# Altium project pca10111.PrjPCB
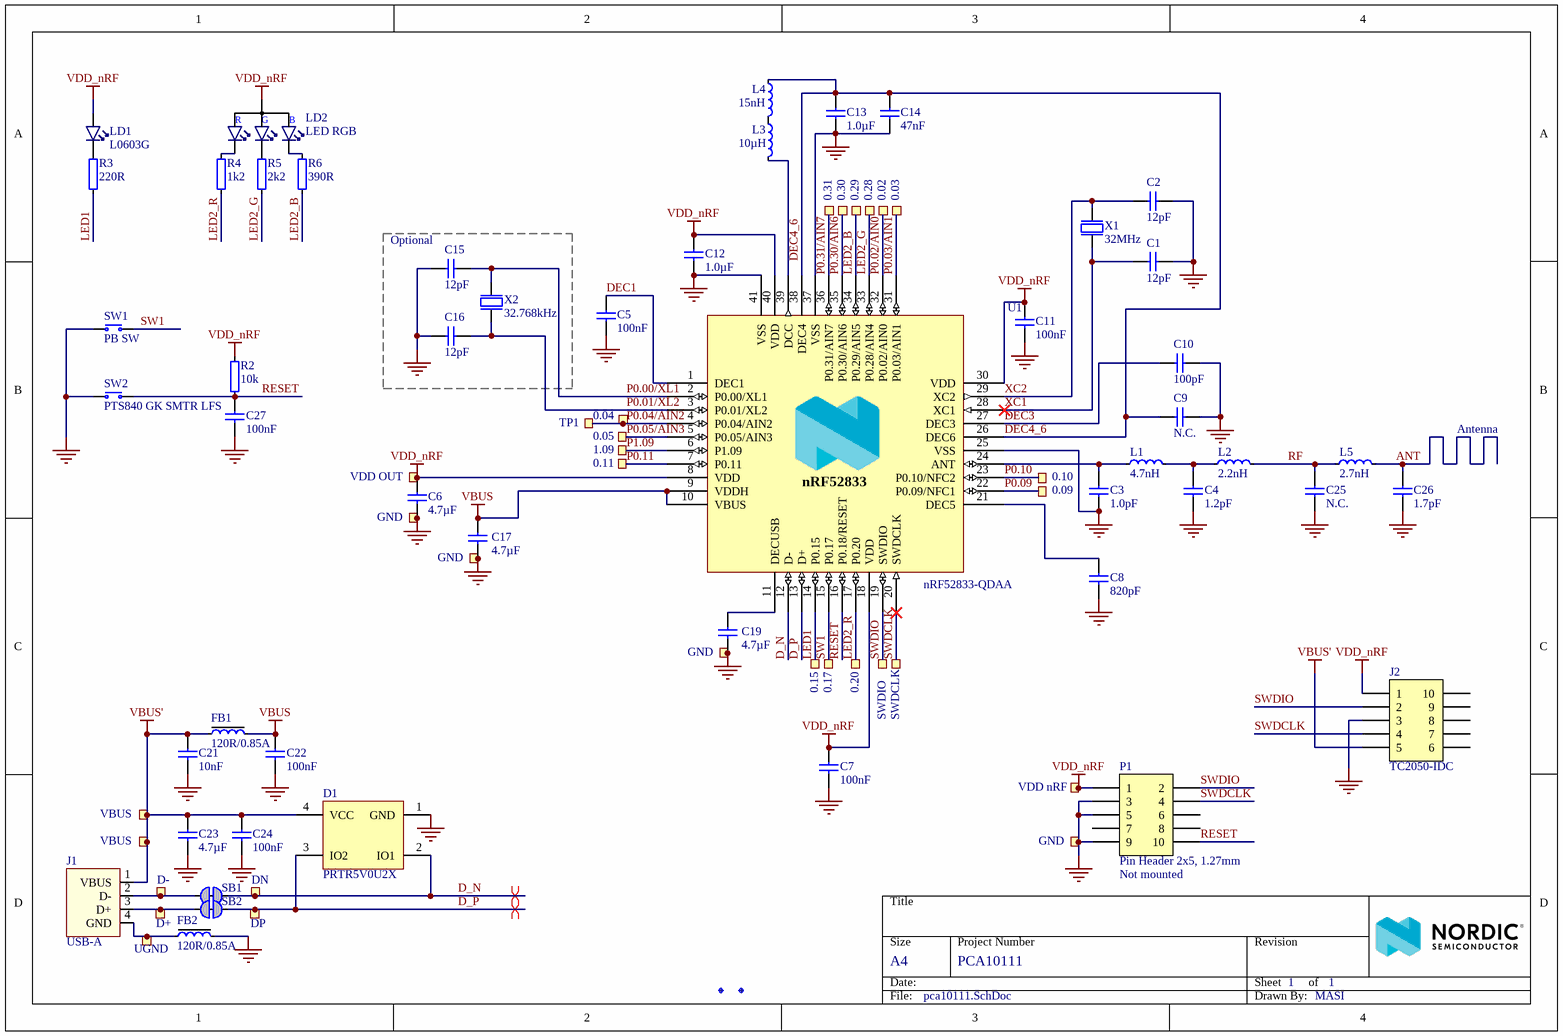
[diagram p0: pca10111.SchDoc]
Author: MASI; BoardThickness: 2.0mm; BoardTitle: nRF52833 USB Dongle; NrOfLayers: 4; Organization: Nordic Semiconductor; PCAName: PCA10111; PCBNumber: 400479; PCBRevision: 0129ERSA; PCBStackup: 4001; ProjectName: Quark Hadron; ProjectNumber: 4452; Rev: 0.2.1; SilkscreenColor: White; SoldermaskColor: Blue; SurfaceFinish: ENIG Gold
1 sheet, 83 parts. Net scope: global (net labels, ports and power ports of the same name join across sheets).
Board files: 400479.PcbDoc, 400479_panel.PcbDoc

## Sheet pca10111.SchDoc: =BoardTitle
size A4; Organization: Nordic Semiconductor; Revision: 0.2.1; SheetNumber: 1; SheetTotal: 1; Author: MASI; CompanyName: Nordic Semiconductor; DrawnBy: MASI

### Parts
0.02  CH  [Castellated_Hole_0.9mm]  (value not drawn)  (no BOM)
0.03  CH  [Castellated_Hole_0.9mm]  (value not drawn)  (no BOM)
0.04  CH  [Castellated_Hole_0.9mm]  (value not drawn)  (no BOM)
0.05  CH  [Castellated_Hole_0.9mm]  (value not drawn)  (no BOM)
0.09  CH  [Castellated_Hole_0.9mm]  (value not drawn)  (no BOM)
0.10  CH  [Castellated_Hole_0.9mm]  (value not drawn)  (no BOM)
0.11  CH  [Castellated_Hole_0.9mm]  (value not drawn)  (no BOM)
0.15  CH  [Castellated_Hole_0.9mm]  (value not drawn)  (no BOM)
0.17  CH  [Castellated_Hole_0.9mm]  (value not drawn)  (no BOM)
0.20  CH  [Castellated_Hole_0.9mm]  (value not drawn)  (no BOM)
0.28  CH  [Castellated_Hole_0.9mm]  (value not drawn)  (no BOM)
0.29  CH  [Castellated_Hole_0.9mm]  (value not drawn)  (no BOM)
0.30  CH  [Castellated_Hole_0.9mm]  (value not drawn)  (no BOM)
0.31  CH  [Castellated_Hole_0.9mm]  (value not drawn)  (no BOM)
1.09  CH  [Castellated_Hole_0.9mm]  (value not drawn)  (no BOM)
C1  12pF  [CAPC0603X03L_C]
C2  12pF  [CAPC0603X03L_C]
C3  1.0pF  [CAPC0603X03L_C]
C4  1.2pF  [CAPC0603X03L_C]
C5  100nF  [CAPC0603X03L_C]
C6  4.7µF  [CAPC1608X06L]
C7  100nF  [CAPC0603X03L_C]
C8  820pF  [CAPC0603X03L_C]
C9  N.C.  [CAPC0603X03L_C_NC]
C10  100pF  [CAPC0603X03L_C]
C11  100nF  [CAPC0603X03L_C]
C12  1.0µF  [CAPC1005X04L]
C13  1.0µF  [CAPC1005X04L]
C14  47nF  [CAPC0603X03L_C]
C15  12pF  [CAPC0603X03L_C]
C16  12pF  [CAPC0603X03L_C]
C17  4.7µF  [CAPC1608X06L]
C19  4.7µF  [CAPC1608X06L]
C21  10nF  [CAPC0603X03L_C]
C22  100nF  [CAPC0603X03L_C]
C23  4.7µF  [CAPC1005X04L]
C24  100nF  [CAPC0603X03L_C]
C25  N.C.  [CAPC0603X03L_C_NC]
C26  1.7pF  [CAPC0603X03L_C]
C27  100nF  [CAPC0603X03L_C]
D1  PRTR5V0U2X  [SOT190P230X110-4L]
D+  Ø1.0mm,SMD  [TP_SMD_D1.0mm]  (value not drawn)  (no BOM)
D-  Ø1.0mm,SMD  [TP_SMD_D1.0mm]  (value not drawn)  (no BOM)
DN  Ø1.0mm,SMD  [TP_SMD_D1.0mm]  (value not drawn)  (no BOM)
DP  Ø1.0mm,SMD  [TP_SMD_D1.0mm]  (value not drawn)  (no BOM)
FB1  120R/0.85A  [INDC0603X03L_C]
FB2  120R/0.85A  [INDC0603X03L_C]
Fid1  Fiducial mark  [Fiducial_Square]  (value not drawn)
Fid2  Fiducial mark  [Fiducial]  (value not drawn)
GND1  GND  [Castellated_Hole_0.9mm]  (no BOM)
GND2  GND  [Castellated_Hole_0.9mm_S]  (no BOM)
GND3  GND  [Castellated_Hole_0.9mm_S]  (no BOM)
GND4  GND  [TP_SMD_D1.0mm]  (no BOM)
J1  USB-A  [USB-A-PCB]
J2  TC2050-IDC  [TC2050-IDC-NLFP]  (no BOM)
L1  4.7nH  [INDC0603X03L_C]
L2  2.2nH  [INDC0603X03L_C]
L3  10µH  [INDC1608X06L]
L4  15nH  [INDC1005X04L]
L5  2.7nH  [INDC0603X03L_C]
LD1  L0603G  [LED_0603_G]
LD2  LED RGB  [LED_RGB_0603]
P1  Pin Header 2x5, 1.27mm  Assembly: Not mounted  [HDR_2x5-SMD-1.27mm-NC]
R2  10k  [RESC0603X03L_C]
R3  220R  [RESC0603X03L_C]
R4  1k2  [RESC0603X03L_C]
R5  2k2  [RESC0603X03L_C]
R6  390R  [RESC0603X03L_C]
SB1  Solderbridge  [Solderbridge_Shorted]  (value not drawn)  (net tie, no BOM)
SB2  Solderbridge  [Solderbridge_Shorted]  (value not drawn)  (net tie, no BOM)
SW1  PB SW  [C&K_PTS810]
SW2  PTS840 GK SMTR LFS  [EVQP7A_J_B_K]
SWDCLK  CH  [Castellated_Hole_0.9mm_D]  (value not drawn)  (no BOM)
SWDIO  CH  [Castellated_Hole_0.9mm_D]  (value not drawn)  (no BOM)
TP1  Ø1.0mm,SMD  [TP_SMD_D1.0mm]  (value not drawn)  (no BOM)
U1  nRF52833-QDAA  [QFN40P500X500X50_HS-41N]
UGND  Ø1.0mm,SMD  [TP_SMD_D1.0mm]  (value not drawn)  (no BOM)
VBUS1  VBUS  [Castellated_Hole_0.9mm]  (no BOM)
VBUS2  VBUS  [TP_SMD_D1.0mm]  (no BOM)
VDD_nRF  Ø1.0mm,SMD  [TP_SMD_D1.0mm]  (value not drawn)  (no BOM)
VDD_OUT  CH  [Castellated_Hole_0.9mm]  (value not drawn)  (no BOM)
X1  32MHz  [BT-XTAL_1612]
X2  32.768kHz  [XTAL_2012]

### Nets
GND: C1.2 C2.2 C3.1 C4.1 C5.2 C6.2 C7.2 C8.2 C9.1 C10.2 C11.2 C12.2 C13.1 C14.2 C15.2 C16.2 C17.2 C19.2 C21.1 C22.1 C23.1 C24.1 C25.2 C26.1 C27.1 D1.1(GND) FB2.2 GND1.1 GND2.1 GND3.1 GND4.1 J2.3 P1.3 P1.5 P1.9 SW1.2(COM) SW2.2(COM) U1.25(VSS) U1.37(VSS) U1.41(VSS) X1.2(GND) X1.4(GND)
VBUS: C17.1 C22.2 FB1.2 U1.9(VDDH) U1.10(VBUS)
VBUS': C21.2 C23.2 C24.2 D1.4(VCC) FB1.1 J1.1(VBUS) J2.5 VBUS1.1 VBUS2.1
VDD_nRF: C6.1 C7.1 C11.1 C12.1 J2.1 LD1.2(A) LD2.4(A) P1.1 R2.2 U1.8(VDD) U1.18(VDD) U1.30(VDD) U1.40(VDD) VDD_nRF.1 VDD_OUT.1
ANT: C26.2 L5.2
D_N: D1.2(IO1) DN.1 SB1.1 U1.12(D-)
D_P: D1.3(IO2) DP.1 SB2.1 U1.13(D+)
DEC1: C5.1 U1.1(DEC1)
DEC3: C10.1 U1.27(DEC3)
DEC4_6: C9.2 C13.2 C14.1 L4.1 U1.26(DEC6) U1.38(DEC4)
LED1: 0.15.1 R3.2 U1.14(P0.15)
LED2_B: 0.29.1 R6.1 U1.34(P0.29/AIN5)
LED2_G: 0.28.1 R5.1 U1.33(P0.28/AIN4)
LED2_R: 0.20.1 R4.2 U1.17(P0.20)
P0.00/XL1: C15.1 U1.2(P0.00/XL1) X2.1(inp)
P0.01/XL2: C16.1 U1.3(P0.01/XL2) X2.2(out)
P0.02/AIN0: 0.02.1 U1.32(P0.02/AIN0)
P0.03/AIN1: 0.03.1 U1.31(P0.03/AIN1)
P0.04/AIN2: 0.04.1 TP1.1 U1.4(P0.04/AIN2)
P0.05/AIN3: 0.05.1 U1.5(P0.05/AIN3)
P0.09: 0.09.1 U1.22(P0.09/NFC1)
P0.10: 0.10.1 U1.23(P0.10/NFC2)
P0.11: 0.11.1 U1.7(P0.11)
P0.30/AIN6: 0.30.1 U1.35(P0.30/AIN6)
P0.31/AIN7: 0.31.1 U1.36(P0.31/AIN7)
P1.09: 1.09.1 U1.6(P1.09)
RESET: C27.2 P1.10 R2.1 SW2.1(N.O) U1.16(P0.18/RESET)
RF: C25.1 L2.2 L5.1
SW1: 0.17.1 SW1.1(N.O) U1.15(P0.17)
SWDCLK: J2.4 P1.4 SWDCLK.1 U1.20(SWDCLK)
SWDIO: J2.2 P1.2 SWDIO.1 U1.19(SWDIO)
XC1: C1.1 U1.28(XC1) X1.1(inp)
XC2: C2.1 U1.29(XC2) X1.3(out)
NetC3_2: C3.2 L1.1 U1.24(ANT)
NetC4_2: C4.2 L1.2 L2.1
NetC8_1: C8.1 U1.21(DEC5)
NetC19_1: C19.1 U1.11(DECUSB)
NetD+_1: D+.1 J1.3(D+) SB2.2
NetD-_1: D-.1 J1.2(D-) SB1.2
NetFB2_1: FB2.1 J1.4(GND) UGND.1
NetL3_1: L3.1 L4.2
NetL3_2: L3.2 U1.39(DCC)
NetLD1_1: LD1.1(C) R3.1
NetLD2_1: LD2.1(C_RED) R4.1
NetLD2_2: LD2.2(C_GREEN) R5.2
NetLD2_3: LD2.3(C_BLUE) R6.2

Not connected (* = marked no-connect by the designer): J2 6 7 8 9 10; P1 6 7 8

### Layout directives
differential pair: D_N, D_P

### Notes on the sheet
- (near C15) Optional
- Antenna

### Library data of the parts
0.02 0.03 0.04 0.05 0.09-0.11 0.15 0.17 0.20 0.28-0.31 1.09 GND1 VBUS1 VDD_OUT = Castellated Hole 0.9mm: Manufacturer: N.A.; Pad Count: 1
C1 C2 C15 C16 = C0201-12p: Capacitor, NP0, ±2%; Manufacturer: N.A.; Part number IPS: 00000007848; Pad Count: 2; Note: 25V
C3 = C0201-1.0p: Capacitor, NP0, ±0.05pF, 50V; Manufacturer: N.A.; Part number IPS: 00000001247; Pad Count: 2
C4 = C0201-1.2p: Capacitor, C0G, ±0.1pF, 50V; Manufacturer: N.A.; Part number IPS: 00000003190; Pad Count: 2; Note: Chip Cap 1%
C5 C7 C11 = C0201-100n: Capacitor, X5R, ±10%; Manufacturer: N.A.; Part number IPS: 00000001248, 00000002505; Pad Count: 2; Note: 16V
C6 C19 = C0603-4µ7-6.3V-X7R: Capacitor, X7R, ±10%, 6.3V; Manufacturer: Samsung Electro-Mechanics America; Manufacturer Part Number: CL10B475KQ8NQNC; Part number IPS: 00000002541; Part number Norautron: N.A.; Pad Count: 2; Artikkelnr Noca: 20039473
C8 = C0201-820p: Capacitor, X7R, ±10%; Manufacturer: N.A.; Part number IPS: 00000001249; Pad Count: 2; Note: 25V
C9 = C0201-N.C.: Not mounted; Manufacturer: N.A.; Assembly: Not mounted; Pad Count: 2; Note: Chip Cap
C10 = C0201-100p: Capacitor, NP0, ±2%, 25V; Manufacturer: Murata; Manufacturer Part Number: GRM0335C1E101GA01; Part number IPS: 00000007853; Pad Count: 2; Artikkelnr Noca: N.A.
C12 C13 = C0402-1µ0: Capacitor, X5R, ±5%, 6.3V; Manufacturer: N.A.; Part number IPS: 00000007786, 00000003457; Pad Count: 2; Artikkelnr Noca: 20039235
C14 = C0201-47n: Capacitor, X5R, ±10%; Manufacturer: N.A.; Part number IPS: 00000001250; Pad Count: 2; Note: 10V
C17 = C0603-4µ7-10V-X7S: Capacitor, X7S, ±10%, 10V; Manufacturer: N.A.; Part number IPS: 00000001779; Pad Count: 2; Artikkelnr Noca: 20030013
C21 = C0201-10n: Capacitor, X7R, ±10%; Manufacturer: N.A.; Part number IPS: 00000003480; Note: 10V; Pad Count: 2
C22 C24 C27 = C0201-100n: Capacitor, X5R, ±10%; Manufacturer: N.A.; Part number IPS: 00000001248, 00000002505; Note: 16V; Pad Count: 2
C23 = C0402-4µ7: Capacitor, X5R, ±20%; Manufacturer: N.A.; Part number IPS: 00000001251, 00000007165; Note: 10V; Artikkelnr Noca: 20039482; Pad Count: 2
C25 = C0201-N.C.: Not mounted; Manufacturer: N.A.; Note: Chip Cap; Assembly: Not mounted; Pad Count: 2
C26 = C0201-1.7p: Chip Cap 0201; Manufacturer: N.A.; Note: Chip Cap 1%; Pad Count: 2
D1 = PRTR5V0U2X: Ultra low capacitance double rail-to-rail ESD protection diode; Manufacturer: NXP Semiconductors; Part number IPS: 00000009951; Note: N.A.; Artikkelnr Noca: 10069015; Pad Count: 4
D+ D- DN DP GND4 TP1 UGND VBUS2 VDD_nRF = TP_SMD_Ø1.0MM: 1.0mm circular SMD testpad; Manufacturer: Nordic Semiconductor; Manufacturer Part Number: N.A.; Pad Count: 1
FB1 FB2 = FB0201-120R@100M-850mA: Ferrite Bead, 120 Ohm @ 100MHz, 850mA, 150 mOhm Max; Manufacturer: Taiyo Yuden; Manufacturer Part Number: BKP0603HS121-T; Part number IPS: 00000001252; Note: Chip EMIFIL Inductor Type Chip Ferrite Bead; Artikkelnr Noca: N.A.; Pad Count: 2
Fid1 = Fid-Mark-Square: Manufacturer: N.A.; Value: N.A.; Pad Count: 1
Fid2 = Fid-Mark: Manufacturer: N.A.; Value: N.A.; Pad Count: 1
GND2 GND3 = Castellated Hole 0.9mm_S: Castellated Hole 0.9mm; Manufacturer: N.A.; Pad Count: 1
J1 = USB-A-PCB: USB-A PCB footprint; Manufacturer: N.A.; Pad Count: 4
J2 = TC2050-IDC-NLFP: CBL PLUG-OF-NAILS 10-PIN; Manufacturer: Tag-Connect LLC; Artikkelnr Noca: N.A.; Pad Count: 10
L1 = L0201-4n7: Inductor, 350mA, ±3%; Manufacturer: Murata; Manufacturer Part Number: LQP03TN4N7H02D; Part number IPS: 00000001792; Pad Count: 2; Note: N.A.
L2 = L0201-2n2: Chip Inductor; Manufacturer: N.A.; Pad Count: 2; Note: High frequency chip inductor ±5%
L3 = L0603-10µ-TDK: Inductor, 250mA, ±20%, 1.05ohm. -55°C ~ 125°C; Manufacturer: TDK Corporation; Manufacturer Part Number: MLZ1608M100WTD25; Pad Count: 2; Note: N.A.
L4 = L0402-15n: Inductor, 320mA, ±5%; Manufacturer: Taiyo Yuden; Manufacturer Part Number: HK100515NJ-T; Part number IPS: 00000001262; Part number Norautron: N.A.; Pad Count: 2; Note: High frequency chip inductor ±10%; Artikkelnr Noca: 33029323
L5 = L0201-2n7: Chip Inductor; Manufacturer: N.A.; Note: High frequency chip inductor ±5%; Pad Count: 2
LD1 = VS 25C7M5: LED, Green, 0603, 573nm, Vf=2.0V, 24mcd, - 40 to +85°C; Manufacturer: Victory Electronics; Part number IPS: 00000001274, 00000009961; Note: N.A.; Artikkelnr Noca: 13019193; Pad Count: 2
LD2 = APHF1608LSEEQBDZGKC: RGB LED 1.60 mm x 0.80 mm SMD; Manufacturer: Kingbright Company LLC; Part number IPS: 00000001254; Note: N.A.; Pad Count: 4
P1 = Pin Header 2x5 SMD, 1.27mm, KS, N.C.: Pin Header 2x5, 1.27mm (50mil), SMD, Keying Shroud; Manufacturer: W-CON; Manufacturer Part Number: 3132-10MS0BK00R1; Note: N.A.; Pad Count: 10
R2 = R0201-10k: Resistor, ±1%, 0.05W; Manufacturer: N.A.; Part number IPS: 00000001255; Note: Chip Res 1%; Pad Count: 2
R3 = R0201-220: Resistor, ±1%, 0.05W; Manufacturer: N.A.; Part number IPS: 00000000863; Note: Chip Res 1%; Pad Count: 2
R4 = R0201-1k2: Resistor, ±1%, 0.05W; Manufacturer: N.A.; Part number IPS: 00000001256; Note: Chip Res 1%; Pad Count: 2
R5 = R0201-2k2: Resistor, ±1%, 0.05W; Manufacturer: N.A.; Part number IPS: 00000001257; Note: Chip Res 1%; Pad Count: 2
R6 = R0201-390: Resistor, ±1%, 0.05W; Manufacturer: N.A.; Part number IPS: 00000001258; Note: Chip Res 1%; Pad Count: 2
SB1 SB2 = Solderbridge Shorted: Shorted Solderbridge; Manufacturer: N.A.; Pad Count: 2
SW1 = PTS810 SJK 250 SMTR LFS: Tactile Switch, SPNO, SMD, 260gf, 4.2x3.2x2.5mm; Manufacturer: C&K; Part number IPS: 00000001259; Note: N.A.; Pad Count: 4
SW2 = PTS840 GK SMTR LFS: Microminiature SMT Switch, Side Actuated; Manufacturer: C&K; Part number IPS: 00000001260; Part number Norautron: N.A.; Note: Tactile Switch, SPST, SMD, 220gf; Artikkelnr Noca: 50019089; Pad Count: 4
SWDCLK SWDIO = Castellated Hole 0.9mm_D: Castellated Hole 0.9mm; Manufacturer: N.A.; Pad Count: 1
U1 = nRF52833-QDAA: Multi-protocol Bluetooth Low Energy, IEEE 802.15.4, ANT and 2.4GHz proprietary system-on-chip; Manufacturer: Nordic Semiconductor; Note: N.A.; Pad Count: 40
X1 = XTAL_SMD1612_32MHz_8pF_General: XTAL SMD 1612, 32MHz, Cl=8pF, Total Tol: ±40ppm; Manufacturer: N.A.; Pad Count: 4; Note: XTAL SMD 32.000MHz
X2 = XTAL_SMD2012_32.768kHz_9pF_General: XTAL SMD 2012, 32.768kHz, Cl=9pF, Total Tol: ±50ppm; Manufacturer: N.A.; Pad Count: 2; Note: XTAL SMD 32.768kHz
